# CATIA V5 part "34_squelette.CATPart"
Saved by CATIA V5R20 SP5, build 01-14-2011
Part number: 34_squelette
Publications: "Point.1", "Droite.2", "Droite.3", "Droite.4", "Point.3", "Plan.1", "Point.4", "Plan.2", "Point.5", "Point.6", "Point.7", "Point.8", "Esquisse.1", "Esquisse.2", "Point.9", "Point.12", "Plan.3", "Point.13", "Point.14", "Plan.4"
Bounding box of the stored display mesh (mm): x -15.801 to 15.801, y 2.913 to 49.163, z -70.57 to 0
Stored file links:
  C:\Documents and Settings\anizard\Bureau\13\34_squelette.CATPart
  C:\Documents and Settings\anizard\Bureau\13\anizard.CATProduct
  D:\Documents\T\2011-2012\CFAO\ThinkMotion\7\SqueletteV.CATPart
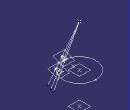
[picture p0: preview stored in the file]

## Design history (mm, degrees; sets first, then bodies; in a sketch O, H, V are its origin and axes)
External parameters (linked from other documents)
  External.delta1 = 68.587 deg
  External.L = 54.7814 mm
  External.module = 2 mm
  External.da1 = 103.4604 mm
  External.da2 = 43.7239 mm
Set1
  Line1: linked copy from another document
  Point1: linked copy from another document
  Line2: linked copy from another document
  Plane1: linked copy from another document
Body1 (main body)
  Point2: type OnCurve, Support Line1, RefPoint Point1, Length 33.3619 {= distance(Point1 ,Plane1 ) +External.da2   /2 + 4mm}
  Line3: type Angle, RefPoint Point2, Curve Line1, Support yz-plane, Start 0, End 74.7814 {= External.L  +20mm}, Angle 68.587 {= External.delta1}
  Line4: type Angle, RefPoint Point2, Curve Line3, Support yz-plane, Start 0, End 74.7814 {= External.L  +20mm}, Angle -2.6147 {= -1.25 * External.module / External.L}
  Line5: type Angle, RefPoint Point2, Curve Line3, Support yz-plane, Start 0, End 74.7814 {= External.L  +20mm}, Angle 2.0918 {= External.module /External.L}
  Point3: type OnCurve, Support Line3, RefPoint Point2, Length 54.7814 {= External.L}
  Plane2: type Normal, Curve Line3, RefPoint Point3
  Point4: type OnCurve, Support Line3, RefPoint Point3, Length 14 {= External.module  *7}
  Plane3: type Normal, Curve Line3, RefPoint Point4
  Point5: type OnCurve, Support Line5, RefPoint Point4, Length 0
  Point6: type OnCurve, Support Line4, RefPoint Point4, Length 0
  Point7: type OnCurve, Support Line5, RefPoint Point3, Length 0
  Point8: type OnCurve, Support Line4, RefPoint Point3, Length 0
  Sketch1 on Plane2, origin (0, -15.7121, -39.5984), H (-1, 0, 0), V (0, -0.931, 0.3651)
    point P1 (-2.3709, -33.4279)
    line L1 (-2.3709, -33.4279) -> (-0.6621, -28.7332)
    point P2 (-0.6621, -28.7332)
    line L2 (-0.6621, -28.7332) -> (0.6621, -28.7332)
    point P3 (0.6621, -28.7332)
    line L3 (0.6621, -28.7332) -> (2.3709, -33.4279)
    point P4 (2.3709, -33.4279)
    line L4 (2.3709, -33.4279) -> (-2.3709, -33.4279)
    reference projected point E1 (0, -28.7332) from Point8
    axis line L5 (-3.7619, -31.2297) -> (3.6633, -31.2297)
    reference projected point E2 (0, -31.2297) from Point2
    point P7 (1.5708, -31.2297)
    point P8 (-1.5708, -31.2297)
    reference projected point E3 (0, -33.2279) from Point7
    reference projected line E4 (0, 93.0973) -> (0, -93.0973) from Line1
    reference projected line E5 (0, 93.0973) -> (0, -93.0973) from Line1
    reference projected line E6 (0, 93.0973) -> (0, -93.0973) from Line1
    angle E6 L1 = 20
    distance P7 P8 = 3.1416 {= External.module  * PI /2}
    distance L4 E3 = 0.2 {= External.module  /10}
    horizontal: L2 H, L4 H, L5 H
    symmetry: P3 P2 E5, P4 P1 E4
    coincidence: L2 E1, L5 E2, P7 L3, P7 L5, P8 L1, P8 L5
  Sketch2 on Plane3, origin (0, -10.3492, -26.6635), H (-1, 0, 0), V (0, -0.931, 0.3651)
    point P1 (-1.7836, -32.647)
    line L1 (-1.7836, -32.647) -> (-0.4929, -29.1009)
    point P2 (-0.4929, -29.1009)
    line L2 (-0.4929, -29.1009) -> (0.4929, -29.1009)
    point P3 (0.4929, -29.1009)
    line L3 (0.4929, -29.1009) -> (1.7836, -32.647)
    point P4 (1.7836, -32.647)
    line L4 (1.7836, -32.647) -> (-1.7836, -32.647)
    reference projected point E1 (0, -29.1009) from Point6
    axis line L5 (-4.3445, -30.9594) -> (4.7226, -30.9594)
    reference projected point E2 (0, -30.9594) from Point2
    point P7 (1.1694, -30.9594)
    point P8 (-1.1694, -30.9594)
    reference projected point E3 (0, -32.447) from Point5
    reference projected line E4 (0, 93.0973) -> (0, -93.0973) from Line1
    reference projected line E5 (0, 93.0973) -> (0, -93.0973) from Line1
    reference projected line E6 (0, 93.0973) -> (0, -93.0973) from Line1
    distance P7 P8 = 2.3387 {= (External.L  -7*External.module )*External.module  *PI/External.L  /2}
    angle L1 E6 = 20
    distance L4 E3 = 0.2 {= External.module  /10}
    horizontal: L2 H, L4 H, L5 H
    symmetry: P3 P2 E5, P4 P1 E4
    coincidence: L2 E1, L5 E2, P7 L3, P7 L5, P8 L1, P8 L5
  Point9: type OnCurve, Support Line3, RefPoint Point3, Length 11.5 {= External.module  *5.75}
  Point10: type OnCurve, Support Line2, RefPoint Point9, Length 0
  Plane4: type Normal, Curve Line2, RefPoint Point10
  Point11: (0, -6, 0), relative to Point10
  Point12: type OnCurve, Support Line2, RefPoint Point10, Length 30
  Plane5: type Normal, Curve Line2, RefPoint Point12
  Circle1: type CtrPt, Start 0, End 180, Center Point10, Support Plane4, RefPoint Point9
